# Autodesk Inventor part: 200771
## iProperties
Created: 2007-11
Part Number: 200771
Material: Acetal Resin, White
Document SubType Name: Modeling
Designer: JJ
Density: 1.42 g/cm^3
Mass: 6.62581 g
Surface Area: 30.1995 cm^2
Volume: 4.66606 cm^3
Description: WORM GEAR - 20 TOOTH
CustomPartVersion: 1
Component Category: Lower Component
Author: JJ
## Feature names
1. Base Body [Revolution]
2. Tooth [Revolution]
3. Tooth Pattern [Circular Pattern]
4. Extrusion1
5. Extrusion2
6. Mirror1
7. Fillet1
